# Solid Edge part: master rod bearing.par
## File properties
Author: Robert a Rhodes jr
Template: Normal.par
Last saved by: CADCIM
Revision: 6
Application: Solid Edge
Accuracy: 0.99
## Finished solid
Body 1: solid body, 4 faces, 4 edges, 0 vertices.
  Faces by surface: cylinder 2, plane 2
  Edges by curve: circle 4
Bounding box of the edges (mm): 52.000 x 52.000 x 70.000, from (-26, -26, -70) to (26, 26, 0).
Cylindrical faces by radius (mm): R23 x1, R26 x1
Planar faces by outward normal: +z 1, -z 1
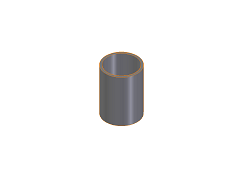
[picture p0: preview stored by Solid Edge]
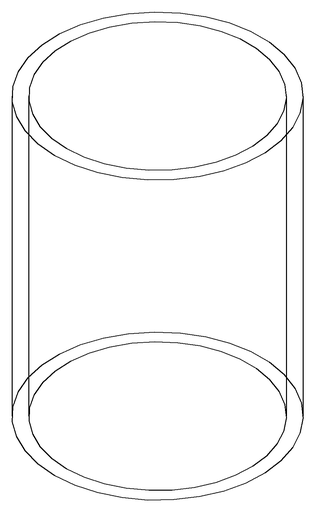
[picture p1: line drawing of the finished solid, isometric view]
